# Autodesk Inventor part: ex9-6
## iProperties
Author: Administrator
Created: 2001-09
Part Number: ex9-6
Document SubType Name: Sheet Metal
Designer: Administrator
Control State: 0
Master: False
Checked Out: False
PropertySet Name: Design Tracking Control
Length Units: 11272
Angle Units: 11279
Time Units: 11290
Mass Units: 11286
Shininess: 3
Angle Display Precision: 2
Document Length Units: 11272
Document Angle Units: 11286
Document Time Units: 11279
Document Mass Units: 11290
Document Length Units Precision: 3
Document Angle Units Precision: 2
Compacted: False
PropertySet Name: _Private Model Information
Density: 0.0
Volumn: 0.0
Area: 0.0
PropertySet Name: Model Information
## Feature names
1. Plate1
2. Bend1
3. Plate2
4. Bend2
5. Cut1
